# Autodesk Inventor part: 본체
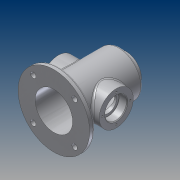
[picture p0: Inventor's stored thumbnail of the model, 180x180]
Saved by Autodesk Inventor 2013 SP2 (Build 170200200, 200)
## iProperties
Created: 2014-12
Part Number: 본체
Material: 알루미늄 6061
Document SubType Name: Modeling
Designer: CADB301
Density: 2.71 g/cm^3
Mass: 478.675 g
Surface Area: 609.694 cm^2
Volume: 176.633 cm^3
Author: CADB301
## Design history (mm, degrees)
sketch "스케치1"
  geometry: L1 (-42.5, 25)-(42.5, 25); L2 (42.5, 25)-(42.5, 0); L3 (42.5, 0)-(-42.5, 0); L4 (-42.5, 0)-(-42.5, 25); L5 (-32.5, 49)-(0, 49); L6 (0, 49)-(0, -49); L7 (0, -49)-(-32.5, -49); L8 (-32.5, -49)-(-32.5, 49); L9 (-52.5, -41)-(0, -41); L10 (0, -49)-(-52.5, -49); L11 (-52.5, -49)-(-52.5, -41); 2 further points
  constraints: 22 end point, 5 parallel, 3 horizontal, 2 midpoint, 2 perpendicular, 1 coincident, 1 point on line
  dimensions: "d0" = 85 distance of L1.start L1.end; "d2" = 25 distance of L1.end L2.end; "d3" = 98 distance of L7.end L5.start; "d4" = 32.5 distance of L6.end L7.end; "d7" = 52.5 distance of L6.end L10.end
revolve "회전1" stored, may be unused: angle "d8" = 90 deg
revolve "회전2" stored, may be unused: angle "d9" = 90 deg
hole "구멍1" diameter "d12" = 55; stored, may be unused: countersink angle "d16" = 90 deg, drill point angle "d18" = 0 deg; dims "d10" = 10, "d11" = 10, "d13" = 6, "d14" = 4, "d15" = 2, "d17" = 93
node "작업 평면1"
sketch "스케치2"
  geometry: C1 r 22.5 at (0, 0); 1 further point
  constraints: 1 centre point, 1 coincident
  dimensions: "d20" = 45 diameter of C1
extrude "돌출1" join sketch "스케치2" stored distance "d21" = 10; taper "d22" = 0 deg
hole "구멍2" diameter "d25" = 27; stored, may be unused: countersink angle "d29" = 90 deg, drill point angle "d31" = 0 deg; dims "d23" = 10, "d24" = 10, "d26" = 6, "d27" = 4, "d28" = 2, "d30" = 93
sketch "스케치3"
  geometry: 2 further points
  constraints: 1 vertical alignment
  dimensions: "d41" = 17.5 distance of point (0, 0) point (0, 17.5)
hole "구멍4" sketch "스케치3" at (0, 17.5) diameter "d42" = 2.459; stored, may be unused: countersink angle "d46" = 90 deg, drill point angle "d48" = 118 deg; dims "d43" = 6, "d44" = 4, "d45" = 2, "d47" = 8
sketch "스케치4"
  geometry: 2 further points
  constraints: 1 vertical alignment
  dimensions: "d52" = 20.5 distance of point (0, 0) point (0, 20.5)
hole "구멍5" sketch "스케치4" at (0, 20.5) diameter "d53" = 2.459; stored, may be unused: countersink angle "d57" = 90 deg, drill point angle "d59" = 118 deg; dims "d54" = 6, "d55" = 4, "d56" = 2, "d58" = 8
sketch "스케치5"
  geometry: C1 r 16 at (0, 0); 2 further points
  constraints: 1 centre point, 1 coincident, 1 vertical alignment
  dimensions: "d63" = 32 diameter of C1; "d64" = 20.5 distance of C1.centre point (0, 20.5)
extrude "돌출2" cut sketch "스케치5" distance "d65" = 12; taper "d66" = 0 deg
hole "구멍6" sketch "스케치5" diameter "d67" = 2.459; stored, may be unused: countersink angle "d71" = 90 deg, drill point angle "d73" = 118 deg; dims "d68" = 6, "d69" = 4, "d70" = 2, "d72" = 8
hole "구멍7" diameter "d79" = 25; stored, may be unused: countersink angle "d83" = 90 deg, drill point angle "d85" = 0 deg; dims "d77" = 10, "d78" = 10, "d80" = 6, "d81" = 4, "d82" = 2, "d84" = 8
chamfer "모따기1" distance "d86" = 1; stored, may be unused: second distance "d87" = 2, angle "d88" = 45 deg
fillet "모깎기1" dims "d89" = 3
fillet "모깎기2" dims "d90" = 0.3
sketch "스케치6" dims "d92" = 86
  geometry: L1 (0, 0)-(42.726, 42.726); L2 (0, 0)-(60.424, 0); 2 further points
  constraints: 4 end point, 1 coincident, 1 equal length, 1 horizontal, 1 point on line, 3 other
  dimensions: "d91" = 45 deg angle of L2 L1
hole "구멍8" sketch "스케치6" at (30.406, 30.406) diameter "d93" = 8; stored, may be unused: countersink angle "d97" = 90 deg, drill point angle "d99" = 0 deg; dims "d94" = 6, "d95" = 4, "d96" = 2, "d98" = 8
node "작업 평면2"
sketch "스케치8"
  geometry: L1 (49, 27.5)-(49, -27.5) reference; 2 further points
  constraints: 1 horizontal alignment, 1 other
  dimensions: "d105" = 89 distance from line of L1 point (-40, 0)
feature "엠보싱1" sketch "스케치8" dims "d0" = 85, "d2" = 25, "d3" = 98, "d4" = 32.5, "d7" = 52.5, "d19" = -106, "d106" = 1, "d107" = 0
node "솔리드1"
pattern_circular "원형 패턴1" dims angle "d50" = 360 deg
pattern_circular "원형 패턴3" dims angle "d75" = 360 deg
mirror "대칭3"
pattern_circular "원형 패턴4" dims angle "d101" = 360 deg
other parameters: "d103" = -32.5
